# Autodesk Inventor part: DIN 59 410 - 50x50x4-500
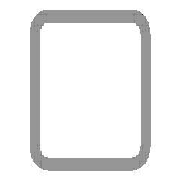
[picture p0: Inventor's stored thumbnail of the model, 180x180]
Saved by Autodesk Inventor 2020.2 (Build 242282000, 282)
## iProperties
Manager: www.cadconsulting.pl
Company: Fabian Stasiak CAD Consulting
Created: 2015-01
Part Number: DIN 59 410 - 50x50x4-500
Material: Stal, miękka
Description: Rurki stalowe o przekroju kwadratowym formowane na gorąco
Document SubType Name: Modellieren
Standard: DIN
Designer: F.Stasiak
Standards Organization: DIN
Language: pl-PL
Size Designation: 50x50x4
Categories: <MemberInstance><Categories><Category DisplayName="Kształtowniki konstrukcyjne" InternalName="089c4875-fa83-4c05-b084-43b9cc11f5ed" Mnemonic="GRDR"><CategoryPar
Stock Number: 50x50x4
Density: 7.85 g/cm^3
Appearance: Częściowo polerowana
Mass: 2781.62 g
Surface Area: 1785.63 cm^2
Volume: 354.346 cm^3
Catalog Web Link: www.expertbooks.pl
_CCFamilyMember: 40
_CCFamilyDisplayName: DIN 59410 (Kwadrat) - Rurki stalowe o przekroju kwadratowym formowane na gorąco
_FrameMemberDoc: Frame Member File
_Version: 15.0.0
_GetPNFromCC: 1
G_W: 50,000 mm
G_H: 50,000 mm
G_L: 500,000 mm
+70772883-221E-492E-818C-8A867A3D80C8+CUTDETAIL4: Wytnij
+6C0DEA11-9028-4435-A260-D7D5E7A07065+CUTDETAIL5: Wytnij
IsCustomPart: 1
Author: F.Stasiak
Subject: Zbiór ćwiczeń. Autodesk Inventor 2020. Kurs Professional
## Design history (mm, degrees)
node "Płaszczyzna początkowa"
node "Płaszczyzna końcowa"
sketch "Szkic"
  geometry: L1 (-17, 25)-(17, 25); L2 (25, 17)-(25, -17); L3 (17, -25)-(-17, -25); L4 (-25, -17)-(-25, 17); L5 (-37.32, 0)-(37.32, 0) reference; L6 (0, -37.32)-(0, 37.32) reference; L7 (-17, 21)-(17, 21); L8 (21, 17)-(21, -17); L9 (17, -21)-(-17, -21); L10 (-21, -17)-(-21, 17); A1 r 8 centre (-17, 17) between (-17, 25) and (-25, 17); A2 r 8 centre (17, 17) between (25, 17) and (17, 25); A3 r 8 centre (17, -17) between (17, -25) and (25, -17); A4 r 8 centre (-17, -17) between (-25, -17) and (-17, -25); A5 r 4 centre (-17, 17) between (-17, 21) and (-21, 17); A6 r 4 centre (17, 17) between (21, 17) and (17, 21); A7 r 4 centre (17, -17) between (17, -21) and (21, -17); A8 r 4 centre (-17, -17) between (-21, -17) and (-17, -21); 3 further points
  constraints: 16 end point, 16 point on circle, 8 centre point, 8 tangent, 6 point on line, 4 parallel, 3 equal radius, 3 perpendicular, 1 horizontal, 7 other
  dimensions: "b" = 50 distance of point (-25, 25) point (25, 25); "msp_r" = 8 radius of A1 (= 2 x ParT); "d8" = 25 distance between parallel lines of L4 L6 (= d9); "d9" = 25 distance between parallel lines of L3 L5 (= 0.5 x b); "d10" = 4 distance between parallel lines of L3 L9 (= ParT)
extrude "Bryła" new body sketch "Szkic" taper "d4" = 0 deg; stored distance "NLG" = 10
node "Driven Length"
  sketch "Sketch2"
    geometry: L1 (0, 0)-(10, 0) reference
    constraints: 2 end point, 1 horizontal
  workplane "Work Plane3"
  sketch "Sketch3"
    geometry: L1 (-2, -25)-(12, -25) reference; L2 (-2, 475)-(12, 475) reference
    dimensions: "d14" = 500 distance between parallel lines of L1 L2 (derived)
node "Płaszczyzna konstrukcyjna7"
feature "Podział4"
node "Płaszczyzna konstrukcyjna8"
feature "Podział5"
body "Solid1"
other parameters: "ParT" = 4, "G_OFFSET_START" = 25 [user parameter; used in 1 equation term], "G_OFFSET_END" = -25 [user parameter; used in 1 equation term], "d11" = -25 (= -G_OFFSET_START), "d12" = 475 (= G_OFFSET_END + B_L), "G_L" = 500 (= d14) [user parameter], "d13" = 90 deg
